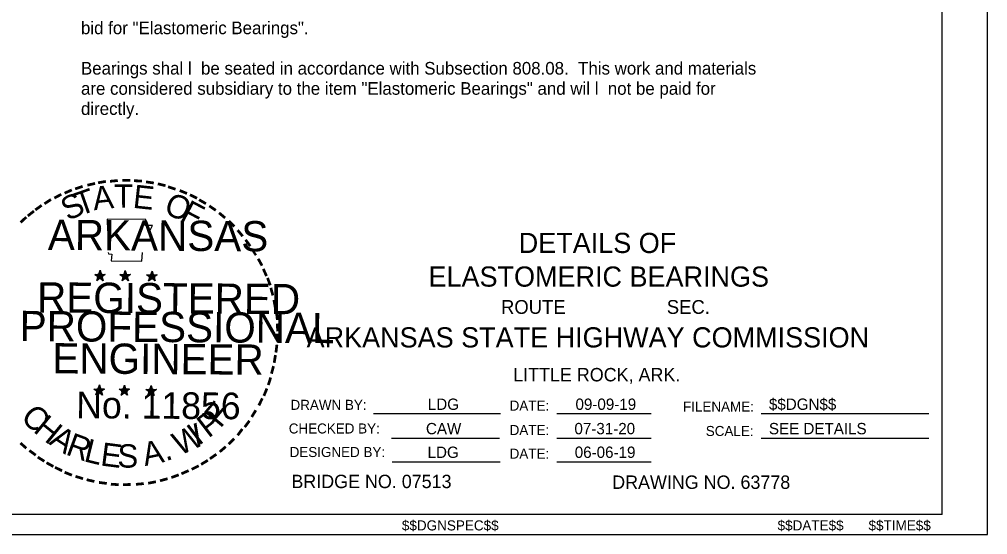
# Model space of a CAD drawing. Extents: x 32334 to 32601, y -901 to -733.
# Drawn here: x 32524.1 to 32600.9, y -900.6 to -859.7 of the extents above; entities that cross this region are included whole.
import ezdxf

# ---------------------------------------------------------------- set-up
doc = ezdxf.new("R2010")
doc.units = 0
for name, color, linetype in [('1', 7, 'Continuous'), ('Level 1', 7, 'Continuous'), ('Level 4', 7, 'Continuous'), ('Level 48', 7, 'Continuous'), ('Level 49', 7, 'Continuous'), ('Level 50', 7, 'Continuous'), ('Level 63', 7, 'Continuous')]:
    doc.layers.add(name, color=color, linetype=linetype)

msp = doc.modelspace()

# ---------------------------------------------------------------- linework, layer by layer
at = {"layer": 'Level 1'}
for q in [(32597.265, -734.628), (32344.32, -898.996)]:
    msp.add_line((32597.265, -898.996), q, dxfattribs=at)
at = {"layer": 'Level 4'}
for p, q in [((32552.203, -891.002), (32562.264, -891.002)), ((32566.721, -891.002), (32574.208, -891.002)), ((32582.925, -891.002), (32596.204, -891.002)), ((32553.623, -892.935), (32562.179, -892.935)), ((32566.721, -892.935), (32574.208, -892.935)), ((32582.925, -892.935), (32596.204, -892.935)), ((32553.683, -894.809), (32562.238, -894.809)), ((32566.721, -894.809), (32574.208, -894.809))]:
    msp.add_line(p, q, dxfattribs=at)
at = {"layer": 'Level 49'}
for p, q in [((32530.096, -879.963), (32530.525, -880.096)), ((32530.096, -879.963), (32530.407, -879.978)), ((32530.096, -879.963), (32530.407, -879.993)), ((32530.096, -879.963), (32530.377, -880.037)), ((32530.096, -879.963), (32530.377, -880.081)), ((32530.096, -879.963), (32530.377, -880.096)), ((32530.096, -879.963), (32530.377, -880.141)), ((32530.274, -880.451), (32530.525, -880.096)), ((32530.274, -880.451), (32530.377, -880.111)), ((32530.274, -880.451), (32530.407, -880.155)), ((32530.274, -880.451), (32530.422, -880.17)), ((32530.525, -879.637), (32530.466, -879.963)), ((32530.525, -879.637), (32530.466, -879.933)), ((32530.525, -879.637), (32530.496, -879.933)), ((32530.525, -880.096), (32530.525, -879.637)), ((32530.525, -879.637), (32530.599, -879.963)), ((32530.525, -879.637), (32530.585, -879.933)), ((32530.525, -879.637), (32530.54, -879.933)), ((32530.94, -879.963), (32530.525, -880.096)), ((32530.777, -880.466), (32530.525, -880.096)), ((32530.94, -879.963), (32530.555, -879.993)), ((32530.94, -879.963), (32530.599, -880.022)), ((32530.94, -879.963), (32530.599, -880.052)), ((32530.777, -880.466), (32530.599, -880.111)), ((32530.777, -880.466), (32530.599, -880.155)), ((32530.777, -880.466), (32530.644, -880.096)), ((32530.94, -879.963), (32530.659, -880.052)), ((32530.94, -879.963), (32530.703, -880.081)), ((32530.94, -879.963), (32530.718, -880.096)), ((32532.094, -879.978), (32532.523, -880.096)), ((32532.094, -879.978), (32532.405, -879.993)), ((32532.094, -879.978), (32532.405, -880.022)), ((32532.094, -879.978), (32532.405, -880.037)), ((32532.094, -879.978), (32532.39, -880.096)), ((32532.094, -879.978), (32532.39, -880.111)), ((32532.094, -879.978), (32532.39, -880.155)), ((32532.272, -880.466), (32532.523, -880.096)), ((32532.272, -880.466), (32532.405, -880.141)), ((32532.272, -880.466), (32532.405, -880.155)), ((32532.272, -880.466), (32532.42, -880.17)), ((32532.523, -879.667), (32532.464, -879.978)), ((32532.523, -879.667), (32532.464, -879.963)), ((32532.523, -879.667), (32532.479, -879.963)), ((32532.523, -880.096), (32532.523, -879.667)), ((32532.523, -879.667), (32532.597, -879.978)), ((32532.523, -879.667), (32532.583, -879.963)), ((32532.523, -879.667), (32532.538, -879.963)), ((32532.938, -879.978), (32532.523, -880.096)), ((32532.775, -880.466), (32532.523, -880.096)), ((32532.938, -879.978), (32532.568, -879.993)), ((32532.938, -879.978), (32532.597, -880.037)), ((32532.938, -879.978), (32532.597, -880.052)), ((32532.775, -880.466), (32532.597, -880.111)), ((32532.775, -880.466), (32532.597, -880.17)), ((32532.775, -880.466), (32532.642, -880.111)), ((32532.938, -879.978), (32532.657, -880.081)), ((32532.938, -879.978), (32532.701, -880.096)), ((32532.938, -879.978), (32532.716, -880.111)), ((32534.211, -879.993), (32534.64, -880.141)), ((32534.211, -879.993), (32534.551, -880.037)), ((32534.211, -879.993), (32534.521, -880.052)), ((32534.211, -879.993), (32534.521, -880.081)), ((32534.211, -879.993), (32534.507, -880.111)), ((32534.211, -879.993), (32534.507, -880.155)), ((32534.211, -879.993), (32534.507, -880.155)), ((32534.373, -880.481), (32534.64, -880.141)), ((32534.373, -880.481), (32534.521, -880.155)), ((32534.64, -879.697), (32534.566, -879.978)), ((32534.64, -879.697), (32534.61, -879.993)), ((32534.64, -879.697), (32534.61, -879.993)), ((32534.64, -880.141), (32534.64, -879.697)), ((32534.64, -879.697), (32534.729, -879.993)), ((32534.64, -879.697), (32534.699, -879.993)), ((32534.64, -879.697), (32534.669, -879.993)), ((32535.054, -879.993), (32534.64, -880.141)), ((32534.877, -880.481), (32534.64, -880.141)), ((32535.054, -879.993), (32534.684, -880.037)), ((32535.054, -879.993), (32534.729, -880.052)), ((32535.054, -879.993), (32534.729, -880.096)), ((32534.877, -880.481), (32534.729, -880.155)), ((32534.877, -880.481), (32534.758, -880.155)), ((32535.054, -879.993), (32534.788, -880.111)), ((32535.054, -879.993), (32534.803, -880.111)), ((32535.054, -879.993), (32534.847, -880.141)), ((32530.274, -880.451), (32530.466, -880.2)), ((32530.274, -880.451), (32530.525, -880.2)), ((32530.274, -880.451), (32530.525, -880.229)), ((32530.777, -880.466), (32530.525, -880.2)), ((32530.777, -880.466), (32530.525, -880.229)), ((32530.777, -880.466), (32530.555, -880.2)), ((32532.272, -880.466), (32532.464, -880.215)), ((32532.272, -880.466), (32532.523, -880.215)), ((32532.272, -880.466), (32532.523, -880.229)), ((32532.775, -880.466), (32532.523, -880.215)), ((32532.775, -880.466), (32532.523, -880.229)), ((32532.775, -880.466), (32532.568, -880.215)), ((32534.373, -880.481), (32534.551, -880.2)), ((32534.373, -880.481), (32534.551, -880.215)), ((32534.373, -880.481), (32534.64, -880.215)), ((32534.373, -880.481), (32534.61, -880.229)), ((32534.373, -880.481), (32534.669, -880.274)), ((32534.877, -880.481), (32534.64, -880.215)), ((32534.877, -880.481), (32534.64, -880.274)), ((32534.877, -880.481), (32534.684, -880.229)), ((32534.877, -880.481), (32534.729, -880.2)), ((32530.037, -889.05), (32530.466, -889.183)), ((32530.037, -889.05), (32530.348, -889.065)), ((32530.037, -889.05), (32530.333, -889.109)), ((32530.037, -889.05), (32530.333, -889.109)), ((32530.037, -889.05), (32530.333, -889.169)), ((32530.037, -889.05), (32530.333, -889.183)), ((32530.037, -889.05), (32530.333, -889.198)), ((32530.185, -889.509), (32530.466, -889.183)), ((32530.185, -889.509), (32530.333, -889.183)), ((32530.185, -889.509), (32530.348, -889.243)), ((32530.185, -889.509), (32530.363, -889.243)), ((32530.185, -889.509), (32530.466, -889.257)), ((32530.185, -889.509), (32530.407, -889.287)), ((32530.185, -889.509), (32530.466, -889.302)), ((32530.466, -888.725), (32530.377, -889.021)), ((32530.466, -888.725), (32530.407, -889.05)), ((32530.466, -888.725), (32530.422, -889.05)), ((32530.703, -889.539), (32530.437, -889.302)), ((32530.466, -889.183), (32530.466, -888.725)), ((32530.466, -888.725), (32530.525, -889.05)), ((32530.466, -888.725), (32530.525, -889.05)), ((32530.466, -888.725), (32530.466, -889.05)), ((32530.881, -889.05), (32530.466, -889.183)), ((32530.703, -889.539), (32530.466, -889.183)), ((32530.703, -889.539), (32530.466, -889.287)), ((32530.703, -889.539), (32530.481, -889.287)), ((32530.881, -889.05), (32530.496, -889.065)), ((32530.881, -889.05), (32530.525, -889.109)), ((32530.881, -889.05), (32530.525, -889.124)), ((32530.703, -889.539), (32530.525, -889.183)), ((32530.703, -889.539), (32530.525, -889.243)), ((32530.881, -889.05), (32530.585, -889.139)), ((32530.703, -889.539), (32530.585, -889.183)), ((32530.881, -889.05), (32530.614, -889.169)), ((32530.881, -889.05), (32530.644, -889.183)), ((32532.035, -889.05), (32532.464, -889.183)), ((32532.035, -889.05), (32532.346, -889.08)), ((32532.035, -889.05), (32532.346, -889.109)), ((32532.035, -889.05), (32532.346, -889.124)), ((32532.035, -889.05), (32532.331, -889.169)), ((32532.035, -889.05), (32532.331, -889.198)), ((32532.035, -889.05), (32532.331, -889.228)), ((32532.183, -889.539), (32532.464, -889.183)), ((32532.183, -889.539), (32532.346, -889.198)), ((32532.183, -889.539), (32532.346, -889.257)), ((32532.183, -889.539), (32532.361, -889.257)), ((32532.183, -889.539), (32532.405, -889.287)), ((32532.183, -889.539), (32532.464, -889.287)), ((32532.183, -889.539), (32532.464, -889.317)), ((32532.464, -888.754), (32532.39, -889.05)), ((32532.464, -888.754), (32532.405, -889.05)), ((32532.464, -888.754), (32532.42, -889.05)), ((32532.701, -889.539), (32532.449, -889.317)), ((32532.464, -889.183), (32532.464, -888.754)), ((32532.464, -888.754), (32532.523, -889.065)), ((32532.464, -888.754), (32532.523, -889.065)), ((32532.464, -888.754), (32532.464, -889.05)), ((32532.864, -889.065), (32532.464, -889.183)), ((32532.701, -889.539), (32532.464, -889.183)), ((32532.701, -889.539), (32532.464, -889.287)), ((32532.701, -889.539), (32532.479, -889.287)), ((32532.864, -889.065), (32532.509, -889.065)), ((32532.864, -889.065), (32532.523, -889.124)), ((32532.864, -889.065), (32532.523, -889.124)), ((32532.701, -889.539), (32532.523, -889.198)), ((32532.701, -889.539), (32532.523, -889.243)), ((32532.864, -889.065), (32532.583, -889.169)), ((32532.701, -889.539), (32532.583, -889.198)), ((32532.864, -889.065), (32532.627, -889.183)), ((32532.864, -889.065), (32532.642, -889.198)), ((32534.151, -889.08), (32534.581, -889.228)), ((32534.151, -889.08), (32534.462, -889.109)), ((32534.151, -889.08), (32534.462, -889.139)), ((32534.151, -889.08), (32534.447, -889.169)), ((32534.151, -889.08), (32534.447, -889.198)), ((32534.151, -889.08), (32534.433, -889.228)), ((32534.151, -889.08), (32534.433, -889.257)), ((32534.314, -889.568), (32534.581, -889.228)), ((32534.314, -889.568), (32534.447, -889.228)), ((32534.314, -889.568), (32534.462, -889.287)), ((32534.314, -889.568), (32534.492, -889.287)), ((32534.314, -889.568), (32534.521, -889.317)), ((32534.314, -889.568), (32534.566, -889.317)), ((32534.314, -889.568), (32534.581, -889.346)), ((32534.581, -888.769), (32534.507, -889.08)), ((32534.581, -888.769), (32534.521, -889.08)), ((32534.581, -888.769), (32534.551, -889.08)), ((32534.817, -889.568), (32534.566, -889.317)), ((32534.817, -889.568), (32534.566, -889.346)), ((32534.581, -889.228), (32534.581, -888.769)), ((32534.581, -888.769), (32534.64, -889.08)), ((32534.581, -888.769), (32534.64, -889.08)), ((32534.581, -888.769), (32534.581, -889.08)), ((32534.995, -889.08), (32534.581, -889.228)), ((32534.817, -889.568), (32534.581, -889.228)), ((32534.817, -889.568), (32534.61, -889.317)), ((32534.995, -889.08), (32534.625, -889.109)), ((32534.995, -889.08), (32534.64, -889.139)), ((32534.995, -889.08), (32534.64, -889.169)), ((32534.817, -889.568), (32534.64, -889.287)), ((32534.817, -889.568), (32534.669, -889.228)), ((32534.817, -889.568), (32534.684, -889.228)), ((32534.995, -889.08), (32534.729, -889.183)), ((32534.995, -889.08), (32534.743, -889.228)), ((32534.995, -889.08), (32534.758, -889.228))]:
    msp.add_line(p, q, dxfattribs=at)
for points in [[(32531.073, -875.582), (32531.117, -876.5)], [(32534.477, -876.5), (32534.669, -876.085), (32534.107, -876.085), (32534.137, -875.612), (32531.073, -875.582)], [(32531.177, -878.217), (32531.191, -878.335), (32531.458, -878.35), (32531.413, -878.897), (32533.826, -878.912), (32533.885, -878.217)], [(32530.525, -879.637), (32530.777, -880.466), (32530.096, -879.963), (32530.94, -879.963), (32530.274, -880.451), (32530.525, -879.637)], [(32532.523, -879.667), (32532.775, -880.466), (32532.094, -879.978), (32532.938, -879.978), (32532.272, -880.466), (32532.523, -879.667)], [(32534.64, -879.697), (32534.877, -880.481), (32534.211, -879.993), (32535.054, -879.993), (32534.373, -880.481), (32534.64, -879.697)], [(32530.466, -888.725), (32530.703, -889.539), (32530.037, -889.05), (32530.881, -889.05), (32530.185, -889.509), (32530.466, -888.725)], [(32532.464, -888.754), (32532.701, -889.539), (32532.035, -889.05), (32532.864, -889.065), (32532.183, -889.539), (32532.464, -888.754)], [(32534.581, -888.769), (32534.817, -889.568), (32534.151, -889.08), (32534.995, -889.08), (32534.314, -889.568), (32534.581, -888.769)]]:
    msp.add_lwpolyline(points, dxfattribs=at)
for centre, radius in [((32530.518, -880.094), 0.207), ((32530.518, -880.094), 0.187), ((32530.518, -880.094), 0.173), ((32530.518, -880.094), 0.159), ((32530.518, -880.094), 0.139), ((32530.518, -880.094), 0.129), ((32530.518, -880.094), 0.119), ((32530.518, -880.094), 0.102), ((32530.518, -880.094), 0.0896), ((32530.518, -880.094), 0.0745), ((32530.518, -880.094), 0.0594), ((32530.518, -880.094), 0.0443), ((32530.518, -880.094), 0.0355), ((32530.518, -880.094), 0.0173), ((32532.519, -880.108), 0.207), ((32532.519, -880.108), 0.187), ((32532.519, -880.108), 0.173), ((32532.519, -880.108), 0.159), ((32532.519, -880.108), 0.139), ((32532.519, -880.108), 0.129), ((32532.519, -880.108), 0.119), ((32532.519, -880.108), 0.102), ((32532.519, -880.108), 0.0896), ((32532.519, -880.108), 0.0745), ((32532.519, -880.108), 0.0594), ((32532.519, -880.108), 0.0443), ((32532.519, -880.108), 0.0355), ((32532.519, -880.108), 0.0173), ((32534.638, -880.137), 0.207), ((32534.638, -880.137), 0.187), ((32534.638, -880.137), 0.173), ((32534.638, -880.137), 0.159), ((32534.638, -880.137), 0.139), ((32534.638, -880.137), 0.129), ((32534.638, -880.137), 0.119), ((32534.638, -880.137), 0.102), ((32534.638, -880.137), 0.0896), ((32534.638, -880.137), 0.0745), ((32534.638, -880.137), 0.0594), ((32534.638, -880.137), 0.0443), ((32534.638, -880.137), 0.0355), ((32534.638, -880.137), 0.0173), ((32530.45, -889.174), 0.207), ((32530.45, -889.174), 0.187), ((32530.45, -889.174), 0.173), ((32530.45, -889.174), 0.159), ((32530.45, -889.174), 0.139), ((32530.45, -889.174), 0.129), ((32530.45, -889.174), 0.119), ((32530.45, -889.174), 0.102), ((32530.45, -889.174), 0.0896), ((32530.45, -889.174), 0.0745), ((32530.45, -889.174), 0.0594), ((32530.45, -889.174), 0.0443), ((32530.45, -889.174), 0.0355), ((32530.45, -889.174), 0.0173), ((32532.451, -889.188), 0.207), ((32532.451, -889.188), 0.187), ((32532.451, -889.188), 0.173), ((32532.451, -889.188), 0.159), ((32532.451, -889.188), 0.139), ((32532.451, -889.188), 0.129), ((32532.451, -889.188), 0.119), ((32532.451, -889.188), 0.102), ((32532.451, -889.188), 0.0896), ((32532.451, -889.188), 0.0745), ((32532.451, -889.188), 0.0594), ((32532.451, -889.188), 0.0443), ((32532.451, -889.188), 0.0355), ((32532.451, -889.188), 0.0173), ((32534.57, -889.217), 0.207), ((32534.57, -889.217), 0.187), ((32534.57, -889.217), 0.173), ((32534.57, -889.217), 0.159), ((32534.57, -889.217), 0.139), ((32534.57, -889.217), 0.129), ((32534.57, -889.217), 0.119), ((32534.57, -889.217), 0.102), ((32534.57, -889.217), 0.0896), ((32534.57, -889.217), 0.0745), ((32534.57, -889.217), 0.0594), ((32534.57, -889.217), 0.0443), ((32534.57, -889.217), 0.0355), ((32534.57, -889.217), 0.0173)]:
    msp.add_circle(centre, radius, dxfattribs=at)
at = {"layer": 'Level 63'}
msp.add_lwpolyline([(32334.224, -900.592), (32600.865, -900.592), (32600.865, -733.016), (32334.224, -733.016)], close=True, dxfattribs=at)

# ---------------------------------------------------------------- texts
at = {"layer": '1'}
for s, p in [('bid for "Elastomeric Bearings".', (32529.01, -860.925)), ('Bearings shal l  be seated in accordance with Subsection 808.08.  This work and materials', (32529.01, -864.125)), ('are considered subsidiary to the item "Elastomeric Bearings" and wil l  not be paid for ', (32529.01, -865.725)), ('directly.', (32529.01, -867.325))]:
    msp.add_text(s, height=1, dxfattribs=at).set_placement(p)
at = {"layer": 'Level 4'}
for s, height, p in [('DETAILS OF', 1.5999, (32563.703, -878.27)), ('ELASTOMERIC BEARINGS', 1.59989, (32556.553, -880.936)), ('ROUTE', 1.0951, (32562.297, -883.093)), ('SEC.', 1.0951, (32575.438, -883.093)), ('ARKANSAS STATE HIGHWAY COMMISSION', 1.59988, (32546.893, -885.755)), ('LITTLE ROCK, ARK.', 1.06089, (32563.264, -888.443)), ('DRAWN BY:', 0.7957, (32545.615, -890.702)), ('DATE:', 0.7957, (32562.983, -890.762)), ('FILENAME:', 0.7957, (32576.723, -890.839)), ('CHECKED BY:', 0.79566, (32545.478, -892.576)), ('DATE:', 0.7957, (32562.983, -892.696)), ('SCALE:', 0.7957, (32578.528, -892.773)), ('DESIGNED BY:', 0.79566, (32545.547, -894.441)), ('DATE:', 0.7957, (32562.983, -894.569)), ('BRIDGE NO. 07513', 1.06089, (32545.684, -896.905)), ('DRAWING NO. 63778', 1.06089, (32571.11, -896.965))]:
    msp.add_text(s, height=height, dxfattribs=at).set_placement(p)
for s, height, p in [('LDG', 0.8984, (32556.5, -890.704)), ('09-09-19', 0.8984, (32568.203, -890.703)), ('$$DGN$$', 0.8984, (32583.53, -890.703)), ('CAW', 0.8984, (32556.349, -892.638)), ('07-31-20', 0.8984, (32568.118, -892.636)), ('SEE DETAILS', 0.89843, (32583.53, -892.636)), ('LDG', 0.8984, (32556.48, -894.513)), ('06-06-19', 0.8984, (32568.144, -894.51))]:
    msp.add_text(s, height=height, rotation=0.0001, dxfattribs=at).set_placement(p)
at = {"layer": 'Level 48'}
for s, height, p in [('$$DGNSPEC$$', 0.80002, (32554.441, -900.26)), ('$$DATE$$', 0.8, (32584.217, -900.26)), ('$$TIME$$', 0.8, (32591.425, -900.26))]:
    msp.add_text(s, height=height, dxfattribs=at).set_placement(p)
at = {"layer": 'Level 49'}
for s, height, rotation, p in [('-', 1.919, 9.82175, (32530.377, -873.451)), ('-', 1.918, 5.49922, (32531.265, -873.333)), ('-', 1.918, 359.78863, (32532.183, -873.244)), ('-', 1.919, 357.34544, (32533.071, -873.273)), ('-', 1.918, 23.90961, (32527.906, -874.25)), ('-', 1.918, 18.77848, (32528.675, -873.925)), ('-', 1.918, 13.23255, (32529.578, -873.643)), ('-', 1.919, 351.76412, (32533.944, -873.347)), ('-', 1.919, 346.80729, (32534.817, -873.481)), ('-', 1.919, 341.9386, (32535.572, -873.688)), ('-', 1.919, 337.45749, (32536.445, -873.954)), ('-', 1.919, 33.66597, (32526.426, -875.049)), ('-', 1.918, 28.39422, (32527.151, -874.62)), ('-', 1.918, 333.72349, (32537.215, -874.265)), ('-', 1.918, 329.24329, (32537.896, -874.62)), ('-', 1.918, 35.83414, (32525.73, -875.523)), ('-', 1.918, 325.46506, (32538.666, -875.079)), ('-', 1.918, 42.56464, (32524.635, -876.47)), ('-', 1.918, 38.55306, (32525.168, -875.982)), ('-', 1.919, 320.13211, (32539.391, -875.582)), ('ARKANSAS', 2.3981, 359.6024, (32526.381, -878.024)), ('-', 1.919, 315.18099, (32540.116, -876.174)), ('-', 1.918, 309.48212, (32540.782, -876.84)), ('-', 1.918, 306.25458, (32541.389, -877.565)), ('-', 1.679, 303.27769, (32541.981, -878.261)), ('-', 1.919, 299.27075, (32542.351, -878.986)), ('-', 1.918, 294.26519, (32542.736, -879.726)), ('REGISTERED', 2.3981, 359.6024, (32525.523, -882.982)), ('-', 1.918, 290.17523, (32543.061, -880.392)), ('-', 1.918, 284.72566, (32543.313, -881.103)), ('-', 1.919, 280.15174, (32543.55, -882.005)), ('PROFESSIONAL', 2.39814, 359.6024, (32524.147, -885.247)), ('-', 1.919, 276.19856, (32543.757, -882.923)), ('-', 1.919, 273.93251, (32543.816, -883.796)), ('-', 1.918, 269.54307, (32543.846, -884.536)), ('ENGINEER', 2.3981, 359.6024, (32526.737, -887.807)), ('-', 1.918, 263.1196, (32543.816, -885.335)), ('-', 1.919, 260.59769, (32543.712, -886.12)), ('-', 1.918, 255.365, (32543.579, -886.934)), ('-', 1.919, 252.47049, (32543.372, -887.807)), ('No. 11856', 2.1102, 359.6024, (32528.631, -891.359)), ('-', 1.918, 247.49106, (32543.106, -888.621)), ('-', 1.919, 244.22211, (32542.765, -889.361)), ('-', 1.919, 238.67365, (32542.292, -890.249)), ('-', 1.919, 233.44764, (32541.833, -891.033)), ('-', 1.919, 233.44764, (32541.27, -891.685)), ('-', 1.918, 225.36773, (32540.708, -892.38)), ('-', 1.918, 138.53622, (32525.257, -893.268)), ('-', 1.918, 144.24874, (32525.952, -893.757)), ('-', 1.918, 220.68749, (32540.086, -892.987)), ('-', 1.919, 147.69218, (32526.603, -894.215)), ('-', 1.919, 211.85149, (32538.769, -894.008)), ('-', 1.918, 215.33873, (32539.406, -893.549)), ('-', 1.918, 151.17279, (32527.284, -894.6)), ('-', 1.918, 154.20259, (32527.935, -894.911)), ('-', 1.918, 203.85401, (32537.348, -894.793)), ('-', 1.919, 206.95924, (32538.103, -894.423)), ('-', 1.919, 158.16361, (32528.675, -895.237)), ('-', 1.918, 162.40066, (32529.504, -895.488)), ('-', 1.919, 167.15791, (32530.348, -895.681)), ('-', 1.919, 190.88816, (32534.921, -895.651)), ('-', 1.918, 195.07669, (32535.794, -895.414)), ('-', 1.918, 200.32082, (32536.608, -895.118)), ('-', 1.919, 172.71786, (32531.265, -895.814)), ('-', 1.919, 176.12067, (32532.168, -895.903)), ('-', 1.919, 181.19416, (32533.056, -895.873)), ('-', 1.918, 185.41906, (32534.033, -895.799))]:
    msp.add_text(s, height=height, rotation=rotation, dxfattribs=at).set_placement(p)
at = {"layer": 'Level 50'}
for s, rotation, p in [('T', 19.33651, (32528.897, -875.345)), ('A', 6.55971, (32530.037, -874.887)), ('T', 0.17131, (32531.635, -874.679)), ('E', 353.7829, (32533.071, -874.679)), ('S', 25.72492, (32527.98, -875.76)), ('O', 338.75668, (32535.498, -875.123)), ('F', 332.36827, (32536.771, -875.641)), ('F', 50.15382, (32540.057, -892.217)), ('C', 314.32777, (32524.147, -891.359)), ('P', 37.37701, (32539.11, -892.987)), ('H', 320.71618, (32525.153, -892.395)), ('A', 327.10458, (32526.396, -893.372)), ('W', 24.60021, (32536.815, -894.363)), ('I', 37.37701, (32538.325, -893.594)), ('R', 339.88139, (32527.728, -894.215)), ('L', 346.26979, (32529.164, -894.763)), ('A', 11.8234, (32534.077, -895.163)), ('E', 352.65819, (32530.496, -895.103)), ('S', 359.04659, (32531.887, -895.266)), ('.', 18.21181, (32535.735, -894.778))]:
    msp.add_text(s, height=1.85, rotation=rotation, dxfattribs=at).set_placement(p)

doc.saveas('drawing.dxf')
